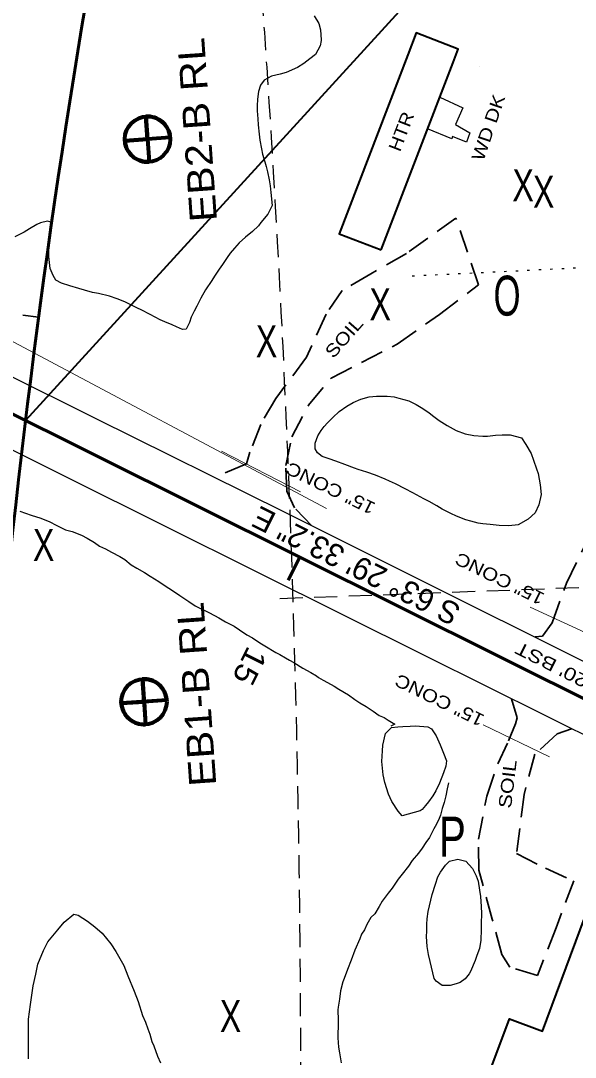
# Model space of a CAD drawing. Extents: x 2399800 to 2400616, y 567347 to 568869.
# Drawn here: x 2400171.1 to 2400344.6, y 568183.3 to 568507.5 of the extents above; entities that cross this region are included whole.
import ezdxf
from ezdxf.enums import TextEntityAlignment as Align

# ---------------------------------------------------------------- set-up
doc = ezdxf.new("R2010")
doc.units = 0
doc.header["$LTSCALE"] = 2.4
for name, pattern in [('DOTTED', [1.5, 0.3, -1.2]), ('LONG_DASHED', [7.5, 6, -1.5]), ('MEDIUM_DASHED', [4.5, 3, -1.5])]:
    doc.linetypes.add(name, pattern=pattern)
for name, color, linetype, lineweight in [('1', 7, 'Continuous', 40), ('11', 7, 'Continuous', 25), ('17', 7, 'MEDIUM_DASHED', 25), ('18', 7, 'Continuous', 13), ('26', 7, 'LONG_DASHED', 35), ('27', 7, 'Continuous', 80), ('3', 7, 'MEDIUM_DASHED', 35), ('38', 7, 'Continuous', 13), ('4', 7, 'Continuous', 35), ('6', 7, 'Continuous', 13), ('61', 7, 'Continuous', 40), ('62', 7, 'Continuous', 60), ('8', 7, 'Continuous', 40)]:
    doc.layers.add(name, color=color, linetype=linetype, lineweight=lineweight)
for name, color, linetype in [('14', 7, 'Continuous'), ('23', 7, 'Continuous'), ('28', 7, 'Continuous'), ('9', 7, 'Continuous')]:
    doc.layers.add(name, color=color, linetype=linetype)

msp = doc.modelspace()

# ---------------------------------------------------------------- linework, layer by layer
at = {"layer": '1'}
msp.add_line((2399965.144, 568485.991), (2400484.477, 568226.976), dxfattribs=at)
at = {"layer": '11', "linetype": 'DOTTED'}
msp.add_line((2400293.6, 568427.731), (2400455.985, 568435.717), dxfattribs=at)
at = {"layer": '11'}
for points in [[(2400262.9, 568509.114), (2400264.327, 568506.643), (2400264.905, 568504.664), (2400265.112, 568501.591), (2400265.074, 568501.373)], [(2400265.074, 568501.373), (2400264.782, 568499.655), (2400263.371, 568497.023), (2400261.518, 568495.667), (2400259.646, 568494.161), (2400257.653, 568492.9), (2400254.17, 568491.301), (2400252.285, 568490.862), (2400249.612, 568490.223), (2400247.311, 568488.926), (2400246.122, 568487.406), (2400245.483, 568485.434), (2400245.169, 568483.039), (2400245.119, 568480.914), (2400245.137, 568479.312), (2400245.272, 568476.858), (2400245.411, 568475.013), (2400245.702, 568472.005), (2400245.916, 568470.15), (2400246.481, 568467.488), (2400246.789, 568465.772), (2400247.467, 568463.399), (2400247.88, 568461.899), (2400248.283, 568460.323), (2400248.857, 568457.735), (2400249.146, 568455.87), (2400249.414, 568453.856), (2400249.793, 568449.77), (2400248.447, 568447.054), (2400246.203, 568444.455), (2400245.532, 568443.4), (2400243.62, 568441.596), (2400241.484, 568439.82), (2400239.507, 568438.099), (2400237.99, 568436.395), (2400236.641, 568434.82), (2400235.706, 568433.496), (2400234.205, 568431.333), (2400233.24, 568429.784), (2400231.739, 568427.621), (2400230.879, 568426.287), (2400228.895, 568423.349), (2400227.494, 568420.792), (2400226.252, 568418.29), (2400225.363, 568416.731), (2400224.499, 568414.789), (2400223.909, 568413.191), (2400222.866, 568411.044), (2400221.714, 568410.966), (2400219.837, 568411.745), (2400218.473, 568412.381), (2400216.241, 568413.358), (2400214.803, 568414.004), (2400211.666, 568415.633)], [(2400211.666, 568415.633), (2400208.81, 568417.074), (2400207.671, 568417.679), (2400204.74, 568419.13), (2400203.741, 568419.641), (2400201.274, 568420.574), (2400198.863, 568421.346), (2400195.469, 568422.172), (2400193.617, 568422.567), (2400191.037, 568423.209), (2400189.28, 568423.745), (2400186.494, 568424.566), (2400183.943, 568425.434), (2400182.095, 568426.437), (2400181.289, 568427.837), (2400180.356, 568430.015), (2400180.249, 568430.943), (2400179.939, 568433.801), (2400179.846, 568437.162), (2400180.066, 568439.418), (2400180.793, 568442.064), (2400180.947, 568444.404), (2400179.564, 568444.889), (2400177.276, 568444.275), (2400176.225, 568443.804), (2400173.913, 568442.432), (2400172.174, 568441.366), (2400169.319, 568439.913)], [(2400170.907, 568354.086), (2400174.459, 568352.88), (2400177.423, 568351.901), (2400180.216, 568350.789), (2400182.249, 568349.769), (2400185.158, 568348.334), (2400187.247, 568347.77), (2400190.192, 568346.639), (2400191.922, 568345.657), (2400194.222, 568344.296), (2400195.782, 568343.18), (2400197.682, 568342.331), (2400199.564, 568341.33), (2400202.168, 568339.932), (2400203.746, 568338.968), (2400205.705, 568337.341), (2400207.435, 568336.358), (2400209.887, 568334.98), (2400211.598, 568333.845), (2400214.317, 568332.125), (2400216.029, 568330.99), (2400218.881, 568329.1), (2400220.877, 568327.777), (2400223.729, 568325.886), (2400225.726, 568324.562), (2400230.231, 568322.316), (2400233.12, 568320.729), (2400235.135, 568319.557), (2400237.891, 568318.141), (2400239.602, 568317.007), (2400241.884, 568315.494), (2400243.614, 568314.512), (2400245.896, 568312.999), (2400247.474, 568312.035), (2400250.915, 568309.919), (2400252.226, 568309.296), (2400253.956, 568308.313), (2400255.249, 568307.538), (2400256.542, 568306.764), (2400259.413, 568305.025), (2400261.865, 568303.645), (2400263.595, 568302.663), (2400264.298, 568302.115), (2400265.743, 568301.321), (2400267.036, 568300.546), (2400269.203, 568299.356), (2400270.629, 568298.411), (2400273.652, 568296.654), (2400275.629, 568295.178), (2400277.207, 568294.215), (2400279.223, 568293.043), (2400281.352, 568291.549), (2400283.197, 568290.244), (2400284.812, 568289.584), (2400286.105, 568288.809), (2400288.101, 568287.486), (2400286.92, 568286.929)], [(2400304.894, 568269.196), (2400304.501, 568267.24), (2400304.089, 568265.132), (2400303.524, 568263.042), (2400302.979, 568261.105), (2400302.415, 568259.015), (2400301.981, 568257.989), (2400301.151, 568256.24), (2400300.357, 568254.796), (2400298.941, 568252.04), (2400297.825, 568250.48), (2400296.691, 568248.769), (2400295.575, 568247.21), (2400293.589, 568244.832), (2400292.454, 568243.12), (2400290.449, 568240.591), (2400289.181, 568239.05), (2400287.291, 568236.198), (2400286.023, 568234.657), (2400284.169, 568232.108), (2400283.206, 568230.53), (2400281.845, 568228.23), (2400280.615, 568226.993), (2400279.424, 568224.826), (2400278.612, 568223.23), (2400277.667, 568221.804), (2400277.178, 568220.322), (2400275.668, 568216.806), (2400274.519, 568213.709), (2400273.388, 568210.764), (2400272.275, 568207.971), (2400271.841, 568206.945), (2400271.184, 568204.096), (2400270.868, 568201.514), (2400270.4, 568198.95), (2400270.308, 568198.191), (2400270.373, 568194.945), (2400270.398, 568192.629), (2400270.364, 568191.091), (2400270.312, 568189.402), (2400270.567, 568186.442), (2400270.818, 568184.715), (2400271.357, 568181.566)], [(2400182.751, 568223.143), (2400184.74, 568225.602), (2400187.749, 568228.106), (2400189.06, 568227.776), (2400192.039, 568225.892), (2400194.352, 568224.089), (2400196.645, 568222.119), (2400199.274, 568218.757), (2400200.84, 568216.37), (2400203.347, 568212.01), (2400204.644, 568208.81), (2400206.591, 568204.012), (2400207.889, 568200.813), (2400209.211, 568196.428), (2400210.131, 568194.289), (2400210.885, 568192.17), (2400211.534, 568190.57), (2400212.102, 568188.305), (2400212.771, 568186.872), (2400213.902, 568183.693), (2400214.823, 568181.554)], [(2400173.603, 568182.88), (2400173.527, 568187.787), (2400173.591, 568195.211), (2400174.161, 568199.871), (2400175.04, 568205.675), (2400175.821, 568209.296), (2400176.54, 568212.417), (2400178.255, 568216.768), (2400179.6, 568219.475), (2400182.751, 568223.143)]]:
    msp.add_lwpolyline(points, dxfattribs=at)
for points in [[(2400327.743, 568377.047), (2400329.144, 568374.96), (2400330.757, 568372.16), (2400331.55, 568370.076), (2400332.488, 568367.365), (2400332.985, 568365.929), (2400333.592, 568362.423), (2400333.948, 568359.331), (2400333.227, 568356.152), (2400332.05, 568353.565), (2400329.895, 568351.64), (2400326.691, 568349.851), (2400323.758, 568349.551), (2400320.8, 568349.634), (2400317.946, 568349.932), (2400315.691, 568350.151), (2400314.203, 568350.422), (2400311.922, 568351.026), (2400310.305, 568351.466), (2400307.474, 568352.522), (2400305.606, 568353.376), (2400302.974, 568354.787), (2400301.276, 568355.771), (2400298.868, 568357.152), (2400297.225, 568357.977), (2400293.744, 568359.88), (2400291.391, 568361.102), (2400288.395, 568362.637), (2400286.527, 568363.49), (2400285.164, 568364.126), (2400282.053, 568365.371), (2400279.437, 568366.323), (2400276.726, 568367.135), (2400275.568, 568367.591), (2400272.522, 568368.752), (2400269.692, 568369.808), (2400267.645, 568370.457), (2400265.468, 568371.275), (2400263.939, 568372.389), (2400263.263, 568373.62), (2400263.274, 568375.446), (2400264.027, 568377.707), (2400265.076, 568379.321), (2400266.001, 568380.57), (2400267.066, 568381.725), (2400268.743, 568383.485), (2400270.739, 568385.355), (2400273.09, 568387.027), (2400275.063, 568388.138), (2400277.485, 568389.191), (2400280.167, 568389.906), (2400282.397, 568390.07), (2400285.749, 568390.088), (2400287.93, 568389.878), (2400289.407, 568389.532), (2400292.482, 568388.596), (2400294.854, 568387.524), (2400296.897, 568386.267), (2400298.921, 568384.859), (2400300.3, 568383.765), (2400302.044, 568382.547), (2400304.497, 568380.931), (2400307.344, 568379.416), (2400310.09, 568378.294), (2400312.84, 568377.782), (2400315.704, 568377.559), (2400317.081, 568377.606), (2400319.639, 568377.956), (2400321.699, 568377.991), (2400324.209, 568377.967)], [(2400290.434, 568258.805), (2400289.158, 568260.349), (2400287.205, 568263.286), (2400286.183, 568265.646), (2400285.007, 568269.259), (2400284.45, 568271.64), (2400284.116, 568275.843), (2400284.288, 568279.137), (2400284.359, 568280.978), (2400285.26, 568284.568), (2400287.106, 568286.424), (2400289.07, 568286.723), (2400290.617, 568286.765), (2400292.942, 568286.866), (2400294.65, 568286.966), (2400298.475, 568286.729), (2400299.625, 568286.049), (2400301.055, 568283.87), (2400302.334, 568281.092), (2400303.404, 568278.495), (2400304.264, 568276.077), (2400304.059, 568274.406), (2400303.334, 568272.259), (2400302.1, 568269.096), (2400300.958, 568266.691), (2400299.994, 568265.113), (2400298.68, 568263.193), (2400297.771, 568262.071), (2400296.693, 568260.815), (2400296.02, 568260.358)], [(2400299.204, 568213.285), (2400298.705, 568215.505), (2400298.233, 568217.952), (2400298.124, 568219.584), (2400298.083, 568221.131), (2400298.126, 568222.744), (2400298.167, 568224.975), (2400298.286, 568226.579), (2400298.575, 568228.933), (2400298.94, 568230.662), (2400299.842, 568234.252), (2400300.858, 568237.519), (2400301.592, 568239.742), (2400302.395, 568241.262), (2400303.974, 568243.459), (2400305.195, 568244.62), (2400307.822, 568245.301), (2400310.368, 568244.681), (2400312.395, 568242.351), (2400313.578, 568240.049), (2400314.228, 568238.427), (2400314.653, 568235.6), (2400314.943, 568233.561), (2400315.179, 568230.448), (2400315.223, 568228.285), (2400315.146, 568225.133), (2400315.15, 568223.283), (2400315.055, 568219.98), (2400314.578, 568217.34), (2400313.777, 568215.203), (2400313.278, 568213.645), (2400312.627, 568212.106), (2400311.958, 568210.414), (2400311.372, 568209.407), (2400310.18, 568207.857), (2400308.579, 568206.742), (2400307.365, 568206.274), (2400305.45, 568205.738), (2400302.982, 568205.731), (2400301.071, 568207.121), (2400300.405, 568207.973)]]:
    msp.add_lwpolyline(points, close=True, dxfattribs=at)
at = {"layer": '17'}
msp.add_line((2400252.161, 568326.829), (2400447.665, 568334.013), dxfattribs=at)
msp.add_arc((2395446.846, 568174.368), 4811.888, 358.84472, 7.18511, dxfattribs=at)
at = {"layer": '18'}
msp.add_line((2400086.216, 568451.054), (2400266.761, 568354.939), dxfattribs=at)
at = {"layer": '26'}
for p in [(2400314.564, 568493.073), (2400314.566, 568493.081)]:
    msp.add_line(p, (2400314.566, 568493.081), dxfattribs=at)
at = {"layer": '27'}
for p, q in [((2400210.318, 568477.564), (2400211.31, 568463.37)), ((2400203.712, 568470.052), (2400203.717, 568469.973)), ((2400217.911, 568470.964), (2400203.717, 568469.973)), ((2400209.213, 568301.623), (2400210.206, 568287.429)), ((2400202.607, 568294.111), (2400202.612, 568294.032)), ((2400216.806, 568295.023), (2400202.612, 568294.032))]:
    msp.add_line(p, q, dxfattribs=at)
for points in [[(2400217.911, 568470.964), (2400210.814, 568470.469), (2400210.318, 568477.564), (2400210.239, 568477.559)], [(2400203.717, 568469.973), (2400210.814, 568470.469), (2400211.31, 568463.37)], [(2400216.806, 568295.023), (2400209.709, 568294.528), (2400209.213, 568301.623), (2400209.134, 568301.618)], [(2400202.612, 568294.032), (2400209.709, 568294.528), (2400210.206, 568287.429)]]:
    msp.add_lwpolyline(points, dxfattribs=at)
for centre in [(2400210.814, 568470.468), (2400209.709, 568294.528)]:
    msp.add_circle(centre, 7.114, dxfattribs=at)
for centre, start, end in [((2400210.814, 568470.468), 4, 94.64426), ((2400210.814, 568470.468), 183.35573, 274), ((2400209.709, 568294.528), 4, 94.64426), ((2400209.709, 568294.528), 183.35573, 274)]:
    msp.add_arc(centre, 7.114, start, end, dxfattribs=at)
at = {"layer": '3', "linetype": 'Continuous', "lineweight": 60}
msp.add_line((2400258.391, 568339.736), (2400254.82, 568332.577), dxfattribs=at)
at = {"layer": '3', "linetype": 'Continuous', "lineweight": 25}
for points in [[(2400483.629, 568239.104), (2400470.246, 568245.798), (2400419.343, 568271.108), (2400362.072, 568299.673), (2400308.009, 568326.642), (2400253.449, 568353.932), (2400194.927, 568382.951), (2400136.831, 568411.76), (2400076.265, 568441.964), (2400023.623, 568468.434), (2399965.535, 568497.344), (2399964.308, 568497.949)], [(2400485.284, 568215.439), (2400462, 568226.988), (2400409.841, 568252.853), (2400354.423, 568280.585), (2400297.876, 568308.829), (2400245.542, 568334.846), (2400186.098, 568364.488), (2400128.133, 568393.345), (2400067.555, 568423.559), (2400013.737, 568450.439), (2399965.96, 568474.329)]]:
    msp.add_lwpolyline(points, dxfattribs=at)
at = {"layer": '3'}
for points in [[(2400262.208, 568349.574), (2400256.772, 568355.159), (2400254.416, 568360.417), (2400254.014, 568368.387), (2400255.959, 568377.421), (2400261.13, 568387.25), (2400268.26, 568395.757), (2400277.737, 568400.682), (2400288.914, 568406.374), (2400302.163, 568415.677), (2400314.26, 568424.904), (2400307.249, 568445.77), (2400291.799, 568434.775), (2400280.599, 568428.325), (2400271.626, 568423.182), (2400266.619, 568415.767), (2400260.508, 568402.255), (2400250.909, 568389.427), (2400246.188, 568381.291), (2400242.84, 568372.593), (2400241.751, 568368.929), (2400231.848, 568364.821)], [(2400332.041, 568314.84), (2400334.345, 568314.995), (2400337.329, 568319.172), (2400341.851, 568331.598), (2400350.923, 568350.281), (2400360.038, 568369.872), (2400367.626, 568392.327), (2400374.356, 568407.662), (2400388.532, 568399.637), (2400403.299, 568390.317), (2400395.415, 568373.154), (2400384.499, 568357.834), (2400375.714, 568349.468), (2400364.629, 568340.414), (2400356.97, 568334.261), (2400351.516, 568328.657), (2400348.55, 568322.878), (2400347.284, 568317.867), (2400347.21, 568313.233), (2400351.163, 568305.115)], [(2400343.425, 568286.079), (2400338.908, 568284.448), (2400331.913, 568278.131), (2400328.589, 568265.547), (2400326.241, 568247.049), (2400335.231, 568242.445), (2400344.075, 568238.469), (2400338.575, 568223.811), (2400332.737, 568208.892), (2400324.101, 568211.546), (2400321.568, 568215.456), (2400318.6, 568226.505), (2400314.365, 568241.83), (2400314.263, 568251.512), (2400316.872, 568265.027), (2400320.322, 568275.082), (2400323.708, 568282.328), (2400325.921, 568287.596), (2400326.4, 568289.513), (2400324.683, 568295.439)]]:
    msp.add_lwpolyline(points, dxfattribs=at)
at = {"layer": '38'}
msp.add_line((2399965.144, 568485.991), (2400484.477, 568226.976), dxfattribs=at)
at = {"layer": '4'}
msp.add_line((2400176.752, 568414.798), (2400171.795, 568415.454), dxfattribs=at)
at = {"layer": '6'}
for p, q in [((2400258.66, 568360.155), (2400233.931, 568372.892)), ((2400353.395, 568313.493), (2400330.494, 568324.157)), ((2400336.483, 568277.327), (2400315.738, 568287.341))]:
    msp.add_line(p, q, dxfattribs=at)
at = {"layer": '61'}
msp.add_line((2400340.726, 568566.615), (2400172.663, 568382.492), dxfattribs=at)
at = {"layer": '62'}
msp.add_line((2399965.144, 568485.991), (2400484.477, 568226.976), dxfattribs=at)
msp.add_arc((2403051.703, 568034.46), 2900, 170.48821, 180.54867, dxfattribs=at)
at = {"layer": '8'}
msp.add_line((2400283.881, 568435.851), (2400306.348, 568494.458), dxfattribs=at)
for points in [[(2400306.348, 568494.458), (2400307.967, 568498.68), (2400294.804, 568503.726), (2400292.163, 568496.835)], [(2400292.163, 568496.835), (2400270.718, 568440.897), (2400283.881, 568435.851)]]:
    msp.add_lwpolyline(points, dxfattribs=at)
at = {"layer": '8', "lineweight": 25}
msp.add_lwpolyline([(2400302.21, 568483.662), (2400309.368, 568480.26), (2400307.09, 568475.076), (2400311.626, 568472.502), (2400310.559, 568469.596), (2400306.215, 568471.308), (2400305.968, 568470.579), (2400298.383, 568473.68)], dxfattribs=at)
at = {"layer": '8'}
msp.add_lwpolyline([(2400377.037, 568144.88), (2400313.925, 568168.365), (2400323.96, 568195.332), (2400334.338, 568191.47), (2400353.556, 568243.115), (2400386.515, 568230.85), (2400367.304, 568179.225), (2400387.079, 568171.866)], close=True, dxfattribs=at)

# ---------------------------------------------------------------- texts
at = {"layer": '11', "width": 0.75}
for p in [(2400328.262, 568451.091), (2400334.692, 568449.03), (2400283.563, 568413.856), (2400248.015, 568402.297), (2400178.317, 568338.571), (2400236.76, 568191.203)]:
    msp.add_text('X', height=10, dxfattribs=at).set_placement(p, align=Align.CENTER)
at = {"layer": '14', "width": 0.75}
msp.add_text('P', height=12.5, dxfattribs=at).set_placement((2400306.163, 568246.09), align=Align.CENTER)
at = {"layer": '23'}
for s, rotation, width, p in [('SOIL', 48.797, 1.2, (2400273.74, 568407.155)), ("SR 1001   PAUL'S PATH RD   20' BST", 153.046, 1.3, (2400380.551, 568286.305)), ('SOIL', 83.17, 1.25, (2400325.393, 568268.578))]:
    msp.add_text(s, height=4, rotation=rotation, dxfattribs=dict(at, width=width)).set_placement(p, align=Align.CENTER)
at = {"layer": '26', "width": 1.2}
for p in [(2400268.914, 568363.097), (2400321.812, 568334.808), (2400302.984, 568296.791)]:
    msp.add_text('15" CONC', height=4, rotation=153.938, dxfattribs=at).set_placement(p, align=Align.CENTER)
at = {"layer": '27', "width": 1.15}
for s, p in [('EB2-B RL', (2400230.518, 568473.672)), ('EB1-B RL', (2400230.315, 568297.121))]:
    msp.add_text(s, height=8.438, rotation=94, dxfattribs=at).set_placement(p, align=Align.CENTER)
at = {"layer": '28'}
for s, rotation, width, p in [('WD DK', 71.094, 1.2, (2400319.276, 568473.479)), ('HTR', 68.951, 1.15, (2400292.034, 568472.186))]:
    msp.add_text(s, height=4, rotation=rotation, dxfattribs=dict(at, width=width)).set_placement(p, align=Align.CENTER)
at = {"layer": '61'}
msp.add_text('S 63° 29\' 33.2" E', height=7, rotation=153.493, dxfattribs=at).set_placement((2400277.604, 568340.169), align=Align.CENTER)
at = {"layer": '61', "width": 1.1}
msp.add_text('15', height=7, rotation=243.493, dxfattribs=at).set_placement((2400239.669, 568307.171), align=Align.CENTER)
at = {"layer": '9', "width": 0.65}
msp.add_text('O', height=12.5, dxfattribs=at).set_placement((2400323.239, 568415.3), align=Align.CENTER)

doc.saveas('drawing.dxf')
